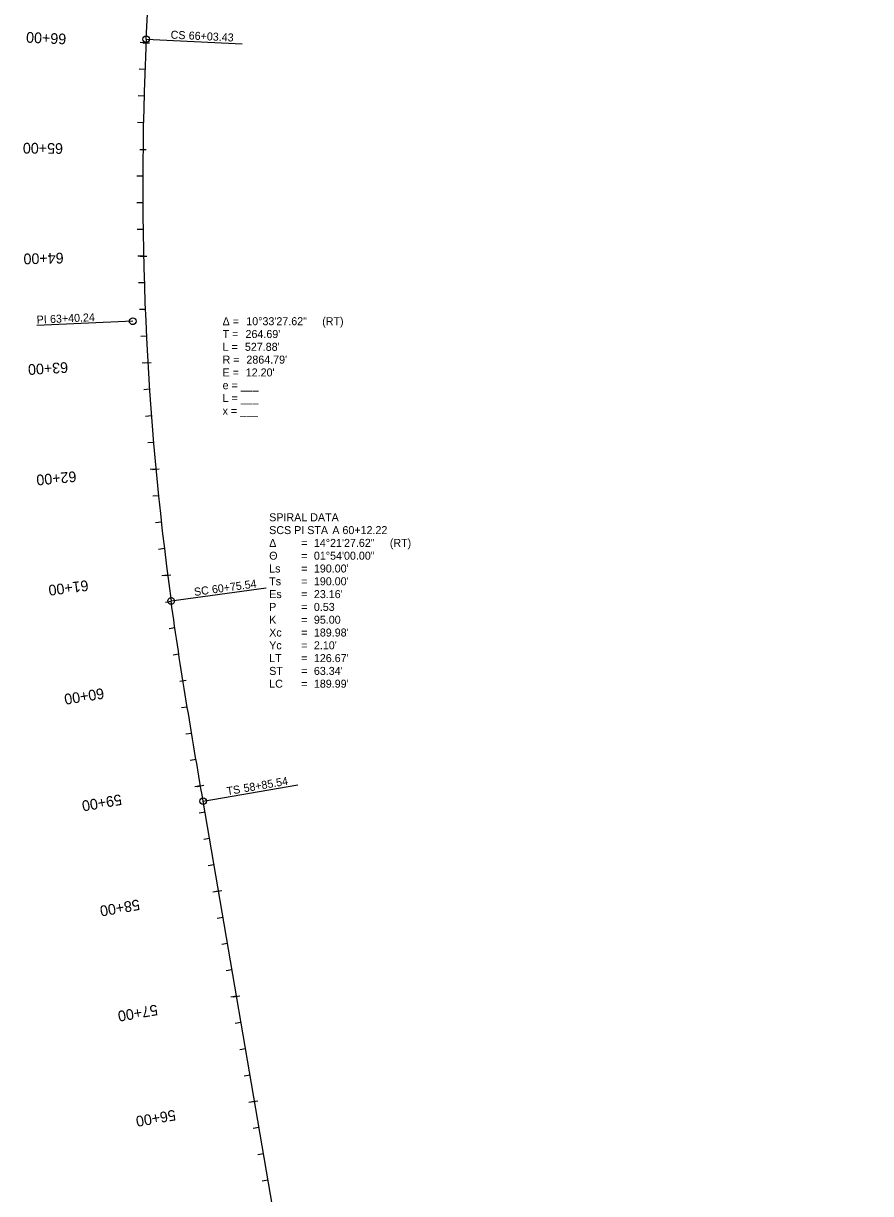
# Model space of a CAD drawing. Extents: x 11526371 to 11527168, y 9590726 to 9599509.
# Drawn here: x 11526371 to 11527166, y 9594030 to 9595127 of the extents above; entities that cross this region are included whole.
import ezdxf

# ---------------------------------------------------------------- set-up
doc = ezdxf.new("R2010")
doc.units = 0
for name, color, linetype in [('Alignment', 7, 'Continuous'), ('Default', 7, 'Continuous'), ('TextAlignment', 7, 'Continuous'), ('TextAlignmentLrg', 7, 'Continuous'), ('TextAlignmentSml', 7, 'Continuous')]:
    doc.layers.add(name, color=color, linetype=linetype)

msp = doc.modelspace()

# ---------------------------------------------------------------- linework, layer by layer
at = {"layer": 'Alignment'}
msp.add_line((11527165.7, 9590741), (11526539.8, 9594397.6), dxfattribs=at)
msp.add_arc((11529348, 9594974.7), 2864.8, 177.2556, 187.8133, dxfattribs=at)
for points in [[(11526486.5, 9595111.8), (11526487.3, 9595127.6), (11526489, 9595159.3), (11526492.3, 9595206.6), (11526495.9, 9595254), (11526498.5, 9595285.6), (11526499.8, 9595301.3)], [(11526539.8, 9594397.6), (11526537.1, 9594413.2), (11526531.8, 9594444.4), (11526524, 9594491.3), (11526516.5, 9594538.2), (11526512, 9594569.5), (11526509.8, 9594585.2)]]:
    msp.add_open_spline(points, degree=3, dxfattribs=at)
at = {"layer": 'Default'}
msp.add_arc((11529348, 9594974.7), 2864.8, 177.2556, 187.8133, dxfattribs=at)
msp.add_open_spline([(11526539.8, 9594397.6), (11526537.1, 9594413.2), (11526531.8, 9594444.4), (11526524, 9594491.3), (11526516.5, 9594538.2), (11526512, 9594569.5), (11526509.8, 9594585.2)], degree=3, dxfattribs=at)
at = {"layer": 'TextAlignment'}
for p, q in [((11526486.5, 9595111.8), (11526576.4, 9595107.5)), ((11526486.5, 9595111.8), (11526576.4, 9595107.5)), ((11526576.4, 9595107.5), (11526576.4, 9595107.5)), ((11526576.4, 9595107.5), (11526576.4, 9595107.5)), ((11526473.8, 9594847.4), (11526383.9, 9594843.5)), ((11526383.9, 9594843.5), (11526383.9, 9594843.5)), ((11526509.8, 9594585.2), (11526599, 9594597.4)), ((11526509.8, 9594585.2), (11526599, 9594597.4)), ((11526599, 9594597.4), (11526599, 9594597.4)), ((11526599, 9594597.4), (11526599, 9594597.4)), ((11526539.8, 9594397.6), (11526628.5, 9594412.8)), ((11526628.5, 9594412.8), (11526628.5, 9594412.8))]:
    msp.add_line(p, q, dxfattribs=at)
for centre in [(11526486.5, 9595111.8), (11526486.5, 9595111.8), (11526473.8, 9594847.4), (11526509.8, 9594585.2), (11526509.8, 9594585.2), (11526539.8, 9594397.6)]:
    msp.add_circle(centre, 3.12, dxfattribs=at)
at = {"layer": 'TextAlignmentLrg'}
for p, q in [((11526486.4, 9595108.4), (11526480.9, 9595108.7)), ((11526480.4, 9595008.5), (11526486.5, 9595008.4)), ((11526484, 9594908.5), (11526478.5, 9594908.3)), ((11526488.1, 9594808.5), (11526482.6, 9594808.2)), ((11526495.6, 9594708.8), (11526490.2, 9594708.3)), ((11526506.6, 9594609.4), (11526501.2, 9594608.7)), ((11526517.9, 9594510), (11526524, 9594511)), ((11526537.4, 9594411.8), (11526532, 9594410.9)), ((11526554.2, 9594313.3), (11526548.9, 9594312.4)), ((11526571.1, 9594214.7), (11526565.7, 9594213.8)), ((11526588, 9594116.1), (11526582.6, 9594115.2))]:
    msp.add_line(p, q, dxfattribs=at)
at = {"layer": 'TextAlignmentSml'}
for p, q in [((11526483.3, 9595108.5), (11526489.4, 9595108.3)), ((11526485.3, 9595083.4), (11526479.8, 9595083.6)), ((11526484.5, 9595058.4), (11526479, 9595058.6)), ((11526483.8, 9595033.4), (11526478.4, 9595033.6)), ((11526480.4, 9595008.5), (11526486.5, 9595008.4)), ((11526483.2, 9594983.4), (11526477.8, 9594983.5)), ((11526483.3, 9594958.4), (11526477.8, 9594958.4)), ((11526483.5, 9594933.4), (11526478.1, 9594933.4)), ((11526480.9, 9594908.4), (11526487.1, 9594908.5)), ((11526484.7, 9594883.5), (11526479.2, 9594883.3)), ((11526485.6, 9594858.5), (11526480.1, 9594858.3)), ((11526486.7, 9594833.5), (11526481.3, 9594833.2)), ((11526485, 9594808.4), (11526491.1, 9594808.7)), ((11526489.6, 9594783.6), (11526484.2, 9594783.2)), ((11526491.4, 9594758.7), (11526485.9, 9594758.2)), ((11526493.4, 9594733.7), (11526487.9, 9594733.3)), ((11526492.5, 9594708.5), (11526498.6, 9594709.1)), ((11526498, 9594683.9), (11526492.6, 9594683.4)), ((11526500.7, 9594659.1), (11526495.2, 9594658.5)), ((11526503.5, 9594634.3), (11526498.1, 9594633.6)), ((11526503.6, 9594609.1), (11526509.6, 9594609.8)), ((11526509.9, 9594584.7), (11526504.5, 9594583.9)), ((11526513.4, 9594559.9), (11526508, 9594559.1)), ((11526517.1, 9594535.2), (11526511.7, 9594534.4)), ((11526517.9, 9594510), (11526524, 9594511)), ((11526524.9, 9594485.8), (11526519.5, 9594484.9)), ((11526529, 9594461.1), (11526523.6, 9594460.2)), ((11526533.2, 9594436.5), (11526527.8, 9594435.6)), ((11526534.4, 9594411.3), (11526540.4, 9594412.4)), ((11526541.6, 9594387.2), (11526536.2, 9594386.3)), ((11526545.8, 9594362.6), (11526540.4, 9594361.6)), ((11526550, 9594337.9), (11526544.6, 9594337)), ((11526551.2, 9594312.8), (11526557.3, 9594313.8)), ((11526558.5, 9594288.6), (11526553.1, 9594287.7)), ((11526562.7, 9594264), (11526557.3, 9594263.1)), ((11526566.9, 9594239.3), (11526561.5, 9594238.4)), ((11526568.1, 9594214.2), (11526574.1, 9594215.2)), ((11526575.3, 9594190.1), (11526570, 9594189.1)), ((11526579.6, 9594165.4), (11526574.2, 9594164.5)), ((11526583.8, 9594140.8), (11526578.4, 9594139.9)), ((11526585, 9594115.6), (11526591, 9594116.7)), ((11526592.2, 9594091.5), (11526586.8, 9594090.6)), ((11526596.4, 9594066.9), (11526591, 9594065.9)), ((11526600.6, 9594042.2), (11526595.3, 9594041.3))]:
    msp.add_line(p, q, dxfattribs=at)

# ---------------------------------------------------------------- texts
at = {"layer": 'TextAlignment'}
for s, rotation, p in [('CS', 357.2556, (11526509.2, 9595112.4)), ('CS', 357.2556, (11526509.2, 9595112.4)), ('66+03.43', 357.2556, (11526526.2, 9595111.6)), ('66+03.43', 357.2556, (11526526.2, 9595111.6)), ('PI ', 2.5344, (11526383.9, 9594845.1)), ('63+40.24', 2.5344, (11526396.4, 9594845.7)), ('60+75.54', 7.8133, (11526548.6, 9594592.2)), ('60+75.54', 7.8133, (11526548.6, 9594592.2)), ('SC', 7.8133, (11526531.8, 9594589.9)), ('SC', 7.8133, (11526531.8, 9594589.9)), ('58+85.54', 9.7133, (11526578.4, 9594405.9)), ('TS', 9.7133, (11526562.5, 9594403.1))]:
    msp.add_text(s, height=7.5, rotation=rotation, dxfattribs=at).set_placement(p)
for s, p in [('Δ = ', (11526558.1, 9594843.7)), ('10°33\'27.62"', (11526580.3, 9594843.7)), (' (RT)', (11526648.7, 9594843.7)), ('T = ', (11526558.1, 9594831.7)), ("264.69'", (11526579.6, 9594831.7)), ('L = ', (11526558.1, 9594819.7)), ("527.88'", (11526579, 9594819.7)), ('R = ', (11526558.1, 9594807.7)), ("2864.79'", (11526580.4, 9594807.7)), ('E = ', (11526558.1, 9594795.7)), ("12.20'", (11526579.8, 9594795.7)), ('e = ___ ', (11526558.1, 9594783.7)), ('L = ___', (11526558.1, 9594771.7)), ('x = ___', (11526558.1, 9594759.7)), ('SPIRAL DATA', (11526601.8, 9594659.9)), ('SCS PI STA ', (11526601.8, 9594647.9)), ('A 60+12.22', (11526661, 9594647.9)), ('Δ', (11526601.8, 9594635.9)), ('= ', (11526631.8, 9594635.9)), ('14°21\'27.62"', (11526643.7, 9594635.9)), (' (RT)', (11526712.1, 9594635.9)), ('Θ ', (11526601.8, 9594623.9)), ('= ', (11526631.8, 9594623.9)), ('01°54\'00.00"', (11526643.7, 9594623.9)), ('Ls', (11526601.8, 9594611.9)), ('= ', (11526631.8, 9594611.9)), ("190.00'", (11526643.7, 9594611.9)), ('Ts', (11526601.8, 9594599.9)), ('= ', (11526631.8, 9594599.9)), ("190.00'", (11526643.7, 9594599.9)), ('Es', (11526601.8, 9594587.9)), ('= ', (11526631.8, 9594587.9)), ("23.16'", (11526643.7, 9594587.9)), ('P', (11526601.8, 9594575.9)), ('= ', (11526631.8, 9594575.9)), ('0.53', (11526643.7, 9594575.9)), ('K', (11526601.8, 9594563.9)), ('= ', (11526631.8, 9594563.9)), ('95.00', (11526643.7, 9594563.9)), ('Xc', (11526601.8, 9594551.9)), ('= ', (11526631.8, 9594551.9)), ("189.98'", (11526643.7, 9594551.9)), ('Yc', (11526601.8, 9594539.9)), ("2.10'", (11526643.7, 9594539.9)), ('LT', (11526601.8, 9594527.9)), ('= ', (11526631.8, 9594539.9)), ("126.67'", (11526643.7, 9594527.9)), ('ST ', (11526601.8, 9594515.9)), ('= ', (11526631.8, 9594527.9)), ("63.34'", (11526643.7, 9594515.9)), ('= ', (11526631.8, 9594515.9)), ('LC', (11526601.8, 9594503.9)), ('= ', (11526631.8, 9594503.9)), ("189.99'", (11526643.7, 9594503.9))]:
    msp.add_text(s, height=7.5, dxfattribs=at).set_placement(p)
at = {"layer": 'TextAlignmentLrg'}
for s, rotation, p in [('65+00', 179.3242, (11526408.5, 9595014.3)), ('60+00', 189.0238, (11526446.1, 9594503.7))]:
    msp.add_text(s, height=10.02, rotation=rotation, dxfattribs=at).set_placement(p)
at = {"layer": 'TextAlignmentSml'}
for s, rotation, p in [('66+00', 177.3242, (11526411.7, 9595116.9)), ('65+00', 179.3242, (11526408.5, 9595014.3)), ('64+00', 181.3242, (11526408.9, 9594911.7)), ('63+00', 183.3242, (11526412.9, 9594809.2)), ('62+00', 185.3242, (11526420.5, 9594706.9)), ('61+00', 187.3242, (11526431.6, 9594604.8)), ('60+00', 189.0238, (11526446.1, 9594503.7)), ('59+00', 189.7023, (11526462.6, 9594404.1)), ('58+00', 189.7133, (11526479.5, 9594305.6)), ('57+00', 189.7133, (11526496.3, 9594207)), ('56+00', 189.7133, (11526513.2, 9594108.4))]:
    msp.add_text(s, height=10.02, rotation=rotation, dxfattribs=at).set_placement(p)

doc.saveas('drawing.dxf')
